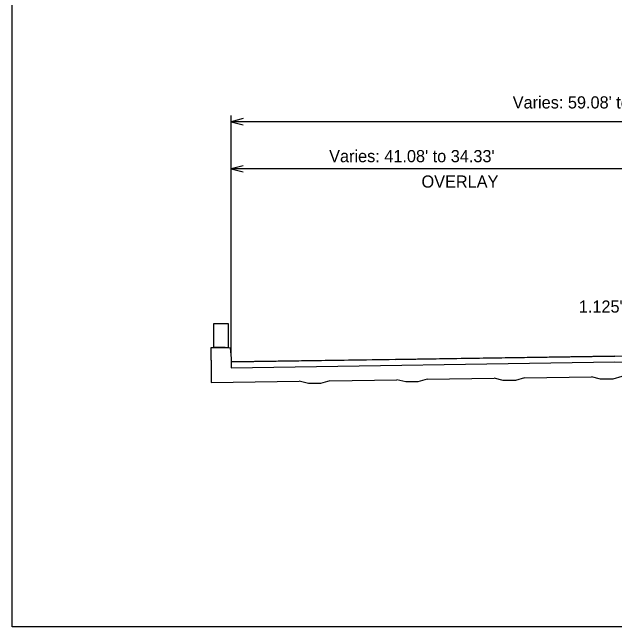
# Model space of a CAD drawing. Extents: x 10133 to 81668, y 7924 to 11018.
# Drawn here: x 10133 to 11122, y 7924 to 8934 of the extents above; entities that cross this region are included whole.
import ezdxf

# ---------------------------------------------------------------- set-up
doc = ezdxf.new("R2010")
doc.units = 0
for name, color, linetype in [('brgConcrete', 7, 'Continuous'), ('brgPreStructureExisting', 7, 'Continuous'), ('dsnStdLineDrawingWt2', 7, 'Continuous'), ('SheetBorder', 7, 'Continuous')]:
    doc.layers.add(name, color=color, linetype=linetype)

msp = doc.modelspace()

# ---------------------------------------------------------------- linework, layer by layer
at = {"layer": 'brgConcrete'}
for p, q in [((10492.2, 8359.5), (11122.5, 8368.9)), ((10492.3, 8364.7), (10492.2, 8359.5)), ((10492.2, 8359.5), (10492.2, 8349.7)), ((10492.2, 8349.7), (11122.5, 8359.2)), ((10492.2, 8349.7), (11122.5, 8359.2))]:
    msp.add_line(p, q, dxfattribs=at)
at = {"layer": 'brgPreStructureExisting'}
for p, q in [((10482.5, 8383), (10463.8, 8383)), ((10487.1, 8382.5), (10482.5, 8383)), ((10762.2, 8363.5), (11062.2, 8368)), ((10459.2, 8362.2), (10459.2, 8325.5)), ((10974.2, 8333.2), (11084.2, 8334.8)), ((10459.2, 8325.5), (10604.2, 8327.6)), ((10654.2, 8328.4), (10764.2, 8330)), ((10814.2, 8330.8), (10924.2, 8332.4))]:
    msp.add_line(p, q, dxfattribs=at)
for points in [[(10463.8, 8383), (10463.8, 8422.2), (10487.1, 8422.2), (10487.1, 8382.5)], [(10463.8, 8383), (10463.8, 8422.2), (10487.1, 8422.2), (10487.1, 8382.5)], [(10459.2, 8362.2), (10459.2, 8383), (10482.5, 8383), (10490.4, 8382.2), (10492.3, 8364.7)], [(10974.2, 8333.2), (10959.2, 8328.7), (10939.2, 8328.7), (10924.2, 8332.4)], [(11134.2, 8335.3), (11119.2, 8331.1), (11099.2, 8331.1), (11084.2, 8334.8)], [(10654.2, 8328.4), (10639.2, 8323.9), (10619.2, 8323.9), (10604.2, 8327.6)], [(10814.2, 8330.8), (10799.2, 8326.3), (10779.2, 8326.3), (10764.2, 8330)]]:
    msp.add_lwpolyline(points, dxfattribs=at)
msp.add_lwpolyline([(10762.2, 8363.5), (10492.2, 8359.5), (10492.2, 8349.7), (11122.5, 8359.2), (11203.2, 8358.6), (11203.2, 8368.4), (11122.5, 8368.9)], close=True, dxfattribs=at)
at = {"layer": 'dsnStdLineDrawingWt2'}
for p, q in [((10492.2, 8373.5), (10492.2, 8764.2)), ((11562.2, 8754.2), (10492.2, 8754.2)), ((10492.2, 8373.5), (10492.2, 8686.6)), ((11203.2, 8676.6), (10492.2, 8676.6)), ((10492.2, 8373.5), (10492.2, 8559))]:
    msp.add_line(p, q, dxfattribs=at)
for points in [[(10512.2, 8759.2), (10492.2, 8754.2), (10512.2, 8749.2)], [(10512.2, 8681.6), (10492.2, 8676.6), (10512.2, 8671.6)]]:
    msp.add_lwpolyline(points, dxfattribs=at)
at = {"layer": 'SheetBorder'}
msp.add_lwpolyline([(10132.5, 9944), (13267.5, 9944), (13267.5, 7924), (10132.5, 7924)], close=True, dxfattribs=at)

# ---------------------------------------------------------------- texts
at = {"layer": 'dsnStdLineDrawingWt2'}
for s, p in [("Varies: 59.08' to 52.33'", (10954.9, 8775.9)), ("Varies: 41.08' to 34.33'", (10653.2, 8687.6)), ('OVERLAY', (10805, 8645.8)), ("1.125'", (11063.5, 8440.3))]:
    msp.add_text(s, height=20, dxfattribs=at).set_placement(p)

doc.saveas('drawing.dxf')
